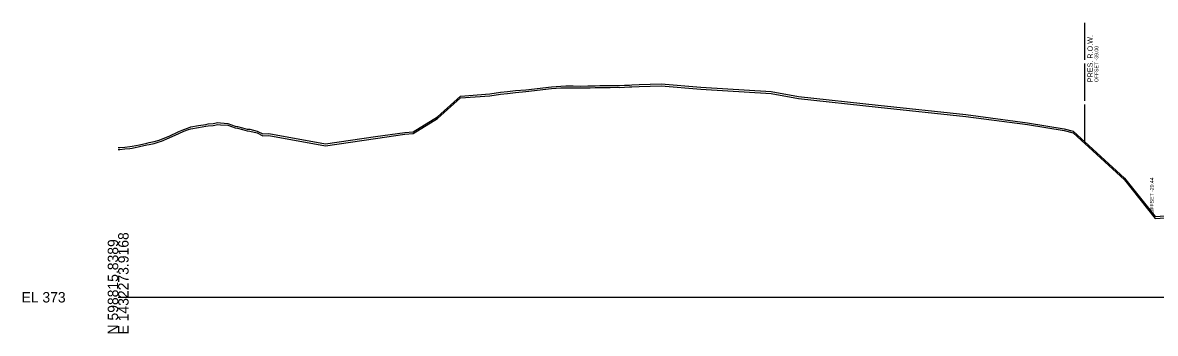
# Model space of a CAD drawing. Extents: x -26 to 2203, y -10 to 12201.
# Drawn here: x -25.7 to 279, y 9990.3 to 10073.8 of the extents above; entities that cross this region are included whole.
import ezdxf

# ---------------------------------------------------------------- set-up
doc = ezdxf.new("R2010")
doc.units = 0
for name, color, linetype in [('DESIGN - SHEET - Light Grid', 7, 'Continuous'), ('DESIGN - TYPICAL - Slope Tie Text', 7, 'Continuous'), ('SURVEY - GROUND - Bottom of Topsoil Layer', 7, 'Continuous'), ('SURVEY - GROUND - Top of Ground', 7, 'Continuous'), ('SURVEY - PROPERTY - ROW Lines', 7, 'Continuous'), ('SURVEY - PROPERTY - ROW Lines Text', 7, 'Continuous')]:
    doc.layers.add(name, color=color, linetype=linetype)

msp = doc.modelspace()

# ---------------------------------------------------------------- linework, layer by layer
at = {"layer": 'DESIGN - SHEET - Light Grid'}
msp.add_line((0, 10000), (300, 10000), dxfattribs=at)
at = {"layer": 'SURVEY - GROUND - Bottom of Topsoil Layer'}
for p, q in [((104.71, 10054.82), (106.92, 10055.08)), ((106.92, 10055.08), (109.66, 10055.32)), ((109.66, 10055.32), (116.56, 10056.12)), ((116.56, 10056.12), (119.06, 10056.3)), ((119.06, 10056.3), (120.41, 10056.36)), ((120.41, 10056.36), (121.69, 10056.33)), ((121.69, 10056.33), (122.39, 10056.34)), ((122.39, 10056.34), (124.47, 10056.3)), ((124.47, 10056.3), (126.34, 10056.32)), ((126.34, 10056.32), (126.96, 10056.33)), ((126.96, 10056.33), (128.32, 10056.38)), ((128.32, 10056.38), (129.6, 10056.41)), ((129.6, 10056.41), (130.29, 10056.44)), ((130.29, 10056.44), (132.38, 10056.45)), ((132.38, 10056.45), (134.25, 10056.46)), ((134.25, 10056.46), (134.87, 10056.44)), ((134.87, 10056.44), (136.23, 10056.52)), ((136.23, 10056.52), (137.51, 10056.55)), ((137.51, 10056.55), (138.2, 10056.6)), ((138.2, 10056.6), (140.16, 10056.7)), ((140.16, 10056.7), (146.03, 10056.86)), ((146.03, 10056.86), (156.76, 10055.96)), ((156.76, 10055.96), (175.66, 10054.79)), ((85.87, 10048.03), (92.11, 10053.6)), ((92.11, 10053.6), (99.98, 10054.21)), ((99.98, 10054.21), (102.88, 10054.65)), ((102.88, 10054.65), (104.71, 10054.82)), ((175.66, 10054.79), (183.02, 10053.49)), ((183.02, 10053.49), (204.42, 10051.16)), ((204.42, 10051.16), (228.02, 10048.65)), ((21.6, 10045.69), (23.55, 10045.97)), ((23.55, 10045.97), (24.19, 10046.11)), ((24.19, 10046.11), (25.52, 10046.21)), ((25.52, 10046.21), (26.83, 10046.49)), ((26.83, 10046.49), (27.5, 10046.37)), ((27.5, 10046.37), (29.51, 10046.24)), ((29.51, 10046.24), (31.45, 10045.55)), ((79.38, 10044.01), (85.87, 10048.03)), ((228.02, 10048.65), (244.61, 10046.44)), ((244.61, 10046.44), (254.5, 10044.81)), ((11.69, 10042.02), (13.69, 10042.83)), ((13.69, 10042.83), (16.29, 10044.04)), ((16.29, 10044.04), (17.62, 10044.64)), ((17.62, 10044.64), (18.92, 10045.08)), ((18.92, 10045.08), (19.59, 10045.31)), ((19.59, 10045.31), (21.6, 10045.69)), ((31.45, 10045.55), (32.1, 10045.46)), ((32.1, 10045.46), (33.43, 10045.09)), ((33.43, 10045.09), (34.73, 10044.73)), ((34.73, 10044.73), (35.41, 10044.69)), ((35.41, 10044.69), (37.37, 10044.21)), ((37.37, 10044.21), (38.94, 10043.44)), ((38.94, 10043.44), (40.52, 10043.51)), ((40.52, 10043.51), (55.77, 10040.74)), ((69.19, 10042.69), (77.12, 10043.83)), ((77.12, 10043.83), (79.38, 10044.01)), ((254.5, 10044.81), (256.89, 10044.19)), ((256.89, 10044.19), (270.69, 10031.54)), ((0, 10039.76), (0.48, 10039.74)), ((0.48, 10039.74), (1.8, 10039.9)), ((1.8, 10039.9), (3.11, 10040.03)), ((3.11, 10040.03), (3.78, 10040.12)), ((3.78, 10040.12), (5.77, 10040.51)), ((5.77, 10040.51), (7.73, 10040.97)), ((7.73, 10040.97), (8.38, 10041.1)), ((8.38, 10041.1), (9.71, 10041.37)), ((9.71, 10041.37), (11.02, 10041.79)), ((11.02, 10041.79), (11.69, 10042.02)), ((55.77, 10040.74), (69.19, 10042.69)), ((270.69, 10031.54), (278.97, 10021.21)), ((278.97, 10021.21), (281.67, 10021.4))]:
    msp.add_line(p, q, dxfattribs=at)
at = {"layer": 'SURVEY - GROUND - Top of Ground'}
for p, q in [((99.98, 10054.71), (102.88, 10055.15)), ((102.88, 10055.15), (104.71, 10055.32)), ((104.71, 10055.32), (106.92, 10055.58)), ((106.92, 10055.58), (109.66, 10055.82)), ((109.66, 10055.82), (116.56, 10056.62)), ((116.56, 10056.62), (119.06, 10056.8)), ((119.06, 10056.8), (120.41, 10056.86)), ((120.41, 10056.86), (121.69, 10056.83)), ((121.69, 10056.83), (122.39, 10056.84)), ((122.39, 10056.84), (124.47, 10056.8)), ((124.47, 10056.8), (126.34, 10056.82)), ((126.34, 10056.82), (126.96, 10056.83)), ((126.96, 10056.83), (128.32, 10056.88)), ((128.32, 10056.88), (129.6, 10056.91)), ((129.6, 10056.91), (130.29, 10056.94)), ((130.29, 10056.94), (132.38, 10056.95)), ((132.38, 10056.95), (134.25, 10056.96)), ((134.25, 10056.96), (134.87, 10056.94)), ((134.87, 10056.94), (136.23, 10057.02)), ((136.23, 10057.02), (137.51, 10057.05)), ((137.51, 10057.05), (138.2, 10057.1)), ((138.2, 10057.1), (140.16, 10057.2)), ((140.16, 10057.2), (146.03, 10057.36)), ((146.03, 10057.36), (156.76, 10056.46)), ((156.76, 10056.46), (175.66, 10055.29)), ((175.66, 10055.29), (183.02, 10053.99)), ((85.87, 10048.53), (92.11, 10054.1)), ((92.11, 10054.1), (99.98, 10054.71)), ((183.02, 10053.99), (204.42, 10051.66)), ((204.42, 10051.66), (228.02, 10049.15)), ((228.02, 10049.15), (244.61, 10046.94)), ((18.92, 10045.58), (19.59, 10045.81)), ((19.59, 10045.81), (21.6, 10046.19)), ((21.6, 10046.19), (23.55, 10046.47)), ((23.55, 10046.47), (24.19, 10046.61)), ((24.19, 10046.61), (25.52, 10046.71)), ((25.52, 10046.71), (26.83, 10046.99)), ((26.83, 10046.99), (27.5, 10046.87)), ((27.5, 10046.87), (29.51, 10046.74)), ((29.51, 10046.74), (31.45, 10046.05)), ((31.45, 10046.05), (32.1, 10045.96)), ((32.1, 10045.96), (33.43, 10045.59)), ((79.38, 10044.51), (85.87, 10048.53)), ((244.61, 10046.94), (254.5, 10045.31)), ((11.69, 10042.52), (13.69, 10043.33)), ((13.69, 10043.33), (16.29, 10044.54)), ((16.29, 10044.54), (17.62, 10045.14)), ((17.62, 10045.14), (18.92, 10045.58)), ((33.43, 10045.59), (34.73, 10045.23)), ((34.73, 10045.23), (35.41, 10045.19)), ((35.41, 10045.19), (37.37, 10044.71)), ((37.37, 10044.71), (38.94, 10043.94)), ((38.94, 10043.94), (40.52, 10044.01)), ((40.52, 10044.01), (55.77, 10041.24)), ((55.77, 10041.24), (69.19, 10043.19)), ((69.19, 10043.19), (77.12, 10044.33)), ((77.12, 10044.33), (79.38, 10044.51)), ((254.5, 10045.31), (256.89, 10044.69)), ((256.89, 10044.69), (270.69, 10032.04)), ((0, 10040.26), (0.48, 10040.24)), ((0.48, 10040.24), (1.8, 10040.4)), ((1.8, 10040.4), (3.11, 10040.53)), ((3.11, 10040.53), (3.78, 10040.62)), ((3.78, 10040.62), (5.77, 10041.01)), ((5.77, 10041.01), (7.73, 10041.47)), ((7.73, 10041.47), (8.38, 10041.6)), ((8.38, 10041.6), (9.71, 10041.87)), ((9.71, 10041.87), (11.02, 10042.29)), ((11.02, 10042.29), (11.69, 10042.52)), ((270.69, 10032.04), (278.97, 10021.71)), ((278.97, 10021.71), (281.67, 10021.9))]:
    msp.add_line(p, q, dxfattribs=at)
at = {"layer": 'SURVEY - PROPERTY - ROW Lines'}
for p, q in [((260, 10063.84), (260, 10073.84)), ((260, 10052.84), (260, 10062.84)), ((260, 10041.84), (260, 10051.84))]:
    msp.add_line(p, q, dxfattribs=at)

# ---------------------------------------------------------------- texts
at = {"layer": 'DESIGN - SHEET - Light Grid'}
for s, p in [('N 598815.8389', (0, 9990)), ('E 1432273.9168', (2.8, 9990))]:
    msp.add_text(s, height=2.8, rotation=90, dxfattribs=at).set_placement(p)
msp.add_text('EL 373', height=2.8, dxfattribs=at).set_placement((-26, 9998.6))
at = {"layer": 'DESIGN - TYPICAL - Slope Tie Text'}
msp.add_text('OFFSET -20.44', height=1, rotation=90, dxfattribs=at).set_placement((278.56, 10022.5))
at = {"layer": 'SURVEY - PROPERTY - ROW Lines Text'}
for s, height, p in [('PRES. R.O.W.', 1.4, (262.15, 10057.84)), ('OFFSET -39.00', 1, (263.65, 10057.84))]:
    msp.add_text(s, height=height, rotation=90, dxfattribs=at).set_placement(p)

doc.saveas('drawing.dxf')
